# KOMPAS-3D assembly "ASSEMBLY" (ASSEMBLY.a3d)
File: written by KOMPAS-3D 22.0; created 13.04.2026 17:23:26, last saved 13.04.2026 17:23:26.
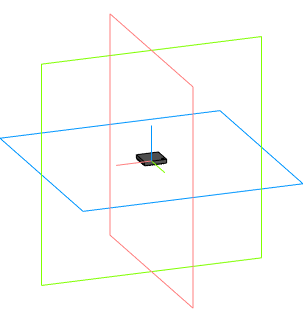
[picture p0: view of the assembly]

Document properties: Автор: Andrey; Полное имя файла: C:\Users\User1\Documents\ASSEMBLY.a3d

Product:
- Component [detail]: Body  | qty 1  | source file: Body.m3d
- Component [detail]: ThermalPin  | qty 1  | source file: ThermalPin.m3d
- Component [detail]: PinsArrayLR  | qty 1  | source file: PinsArrayLR.m3d
- Component [detail]: PinsArrayTB  | qty 1  | source file: PinsArrayTB.m3d
- Part/product: ASSEMBLY

Referenced files in C:\Users\User1\Documents\: Body.m3d, ThermalPin.m3d, PinsArrayLR.m3d, PinsArrayTB.m3d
